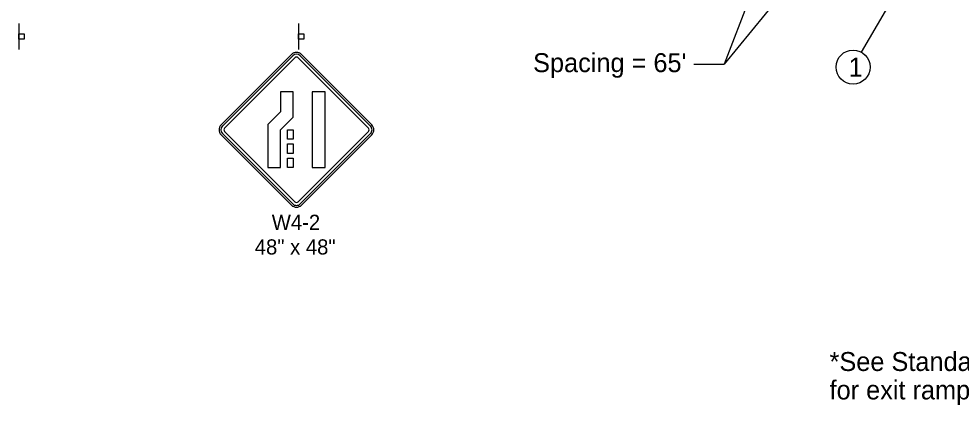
# Model space of a CAD drawing. Extents: x 10133 to 81668, y 4177 to 11018.
# Drawn here: x 25491 to 26486, y 8820 to 9228 of the extents above; entities that cross this region are included whole.
import ezdxf

# ---------------------------------------------------------------- set-up
doc = ezdxf.new("R2010")
doc.units = 0
for name, color, linetype in [('dsnNonPlotable', 7, 'Continuous'), ('dsnStdNote', 7, 'Continuous'), ('Level 1', 7, 'Continuous'), ('Level 12', 7, 'Continuous')]:
    doc.layers.add(name, color=color, linetype=linetype)

msp = doc.modelspace()

# ---------------------------------------------------------------- linework, layer by layer
at = {"layer": 'dsnNonPlotable'}
for p, q in [((25490.62, 9223.06), (25490.62, 9195.56)), ((25786.01, 9223.06), (25786.01, 9195.56)), ((25778.69, 9190.53), (25704.44, 9116.28)), ((25704.45, 9116.28), (25778.69, 9190.53)), ((25705.77, 9114.95), (25780.02, 9189.2)), ((25782.23, 9186.99), (25707.98, 9112.74)), ((25778.69, 9190.53), (25778.69, 9190.53)), ((25782.23, 9186.99), (25782.23, 9186.99)), ((25860.01, 9112.74), (25785.76, 9186.99)), ((25787.97, 9189.2), (25862.22, 9114.95)), ((25789.3, 9190.53), (25863.55, 9116.28)), ((25863.55, 9116.28), (25789.3, 9190.53)), ((25704.44, 9105.67), (25778.69, 9031.43)), ((25778.69, 9031.43), (25704.45, 9105.67)), ((25780.02, 9032.75), (25705.77, 9107)), ((25707.98, 9109.21), (25782.23, 9034.96)), ((25785.76, 9034.96), (25860.01, 9109.21)), ((25862.22, 9107), (25787.97, 9032.75)), ((25863.55, 9105.67), (25789.3, 9031.43)), ((25789.3, 9031.43), (25863.55, 9105.67))]:
    msp.add_line(p, q, dxfattribs=at)
for points in [[(25490.72, 9206.61), (25490.72, 9212.23), (25496.34, 9212.23), (25496.34, 9206.61)], [(25786.11, 9206.61), (25786.11, 9212.23), (25791.73, 9212.23), (25791.73, 9206.61)], [(25766.99, 9129.82), (25753.74, 9116.57), (25753.74, 9070.98), (25767.24, 9070.98), (25767.24, 9110.98), (25780.49, 9124.23), (25780.49, 9150.98), (25766.99, 9150.98)], [(25800.75, 9150.98), (25800.75, 9070.98), (25814.25, 9070.98), (25814.25, 9150.98)], [(25774.49, 9110.98), (25780.49, 9110.98), (25780.49, 9100.98), (25774.49, 9100.98)], [(25774.49, 9095.98), (25780.49, 9095.98), (25780.49, 9085.98), (25774.49, 9085.98)], [(25774.49, 9080.98), (25780.49, 9080.98), (25780.49, 9070.98), (25774.49, 9070.98)]]:
    msp.add_lwpolyline(points, close=True, dxfattribs=at)
for points in [[(25780.02, 9189.2), (25705.77, 9114.95)], [(25782.23, 9186.99), (25707.98, 9112.74)], [(25860.01, 9112.74), (25785.76, 9186.99)], [(25862.22, 9114.95), (25787.97, 9189.2)], [(25705.77, 9107), (25780.02, 9032.75)], [(25707.98, 9109.21), (25782.23, 9034.96)], [(25785.76, 9034.96), (25860.01, 9109.21)], [(25787.97, 9032.75), (25862.22, 9107)]]:
    msp.add_lwpolyline(points, dxfattribs=at)
for centre, radius, start, end in [((25783.99, 9185.22), 7.5, 45.00026, 135.00001), ((25783.99, 9185.22), 7.5, 45.00026, 135.00001), ((25783.99, 9185.22), 5.63, 45.00026, 135.00001), ((25783.99, 9185.22), 5.63, 45.00026, 135.00001), ((25783.99, 9185.22), 2.5, 45.00026, 135.00001), ((25783.99, 9185.22), 2.5, 45.00026, 135.00001), ((25709.75, 9110.98), 7.5, 135.0002, 224.99984), ((25709.75, 9110.98), 7.5, 135.0002, 224.99984), ((25709.75, 9110.98), 5.63, 135.0002, 224.99984), ((25709.75, 9110.98), 5.63, 135.0002, 224.99984), ((25709.75, 9110.98), 2.5, 135.0002, 224.99984), ((25709.75, 9110.98), 2.5, 135.0002, 224.99984), ((25858.24, 9110.98), 2.5, 315.00005, 45.00026), ((25858.24, 9110.98), 2.5, 315.00005, 45.00026), ((25858.24, 9110.98), 5.63, 315.00005, 45.00026), ((25858.24, 9110.98), 5.63, 315.00005, 45.00026), ((25858.24, 9110.98), 7.5, 315.00005, 45.00026), ((25858.24, 9110.98), 7.5, 315.00005, 45.00026), ((25783.99, 9036.73), 7.5, 224.99984, 315.00005), ((25783.99, 9036.73), 7.5, 224.99984, 315.00005), ((25783.99, 9036.73), 5.63, 224.99984, 315.00005), ((25783.99, 9036.73), 5.63, 224.99984, 315.00005), ((25783.99, 9036.73), 2.5, 224.99984, 315.00005), ((25783.99, 9036.73), 2.5, 224.99984, 315.00005)]:
    msp.add_arc(centre, radius, start, end, dxfattribs=at)
at = {"layer": 'dsnStdNote'}
for p, q in [((26291.57, 9324.82), (26236.03, 9180.33)), ((26344.36, 9312.86), (26236.03, 9180.33)), ((26450.79, 9312.23), (26380.71, 9192.98)), ((26204.03, 9180.33), (26236.03, 9180.33))]:
    msp.add_line(p, q, dxfattribs=at)
at = {"layer": 'Level 12'}
msp.add_circle((26372.16, 9177.14), 18, dxfattribs=at)

# ---------------------------------------------------------------- texts
at = {"layer": 'dsnNonPlotable'}
for s, p in [('W4-2', (25757.89, 9005.3)), ('48" x 48"', (25739.93, 8979.3))]:
    msp.add_text(s, height=16, dxfattribs=at).set_placement(p)
at = {"layer": 'dsnStdNote'}
msp.add_text("Spacing = 65'", height=20, dxfattribs=at).set_placement((26034.04, 9171.82))
at = {"layer": 'Level 1'}
for s, p in [('*See Standard Road Plan TC-420', (26347.29, 8856.32)), ('for exit ramp details.', (26347.29, 8826.32))]:
    msp.add_text(s, height=20, dxfattribs=at).set_placement(p)
at = {"layer": 'Level 12'}
msp.add_text('1', height=20, dxfattribs=at).set_placement((26367.42, 9167.14))

doc.saveas('drawing.dxf')
